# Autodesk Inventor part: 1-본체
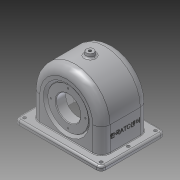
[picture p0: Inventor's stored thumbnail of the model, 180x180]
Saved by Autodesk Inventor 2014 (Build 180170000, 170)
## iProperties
Created: 2015-09
Part Number: 1-본체
Material: 알루미늄 6061
Document SubType Name: Modeling
Designer: Administrator
Density: 2.71 g/cm^3
Appearance: 알루미늄 - 평지
Mass: 723.361 g
Surface Area: 890.236 cm^2
Volume: 266.923 cm^3
Author: Administrator
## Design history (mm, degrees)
sketch "스케치2"
  geometry: L1 (57, 0)-(57, 47); L2 (-57, 47)-(-57, 0); L3 (-57, 0)-(57, 0); A1 r 57 centre (0, 47) between (57, 47) and (-57, 47); 1 further point
  constraints: 6 end point, 2 point on circle, 2 tangent, 1 centre point, 1 midpoint, 1 parallel, 1 perpendicular, 1 vertical, 1 vertical alignment
  dimensions: "d0" = 47 distance of A1.centre point (0, 0); "d1" = 57 radius of A1
extrude "돌출1" new body sketch "스케치2" distance "d2" = 38.5; taper "d3" = 0 deg
sketch "스케치4"
  geometry: L1 (70, -7)-(-70, -7); L2 (-70, -7)-(-70, 0); L3 (-70, 0)-(70, 0); L4 (70, 0)-(70, -7); L5 (57, 0)-(-57, 0) reference; 3 further points
  constraints: 8 end point, 2 midpoint, 2 parallel, 1 collinear, 1 horizontal, 1 perpendicular, 1 vertical alignment
  dimensions: "d6" = 7 distance of L1.end L2.end; "d7" = 140 distance of L2.end L3.end
extrude "돌출2" join sketch "스케치4" distance "d8" = 52; taper "d9" = 0 deg
sketch "스케치5"
  geometry: L1 (51, 0)-(51, -47); L2 (-51, -47)-(-51, 0); L3 (-51, 0)-(51, 0); L4 (-70, 0)-(70, 0) reference; L5 (57, -47)-(57, -7) reference; A1 r 51 centre (0, -47) between (-51, -47) and (51, -47); A2 r 57 centre (0, -47) between (-57, -47) and (57, -47) reference; 1 further point
  constraints: 6 end point, 2 point on circle, 2 tangent, 1 centre point, 1 collinear, 1 concentric, 1 parallel, 1 perpendicular, 1 vertical
  dimensions: "d10" = 6 distance between parallel lines of L5 L1
extrude "돌출3" cut sketch "스케치5" distance "d11" = 33.5; taper "d12" = 0 deg
sketch "스케치6"
  geometry: L1 (-33.5, 47)-(-33.5, 86.747); L2 (-33.5, 86.747)-(-19.5, 75); L3 (-19.5, 75)-(-19.5, 47); L4 (-19.5, 47)-(-33.5, 47); L5 (33.5, 0)-(-33.5, 0) reference; L6 (-33.5, 98)-(-33.5, 47) reference; L7 (-38.5, 104)-(-38.5, 47) reference; 1 further point
  constraints: 8 end point, 1 collinear, 1 parallel, 1 perpendicular, 1 vertical
  dimensions: "d13" = 47 distance between parallel lines of L4 L5; "d14" = 56 diameter of L2.end L4; "d15" = 50 deg angle of L2 L3; "d16" = 19 distance between parallel lines of L3 L7
revolve "회전1" sketch "스케치6" stored, may be unused: angle "d17" = 90 deg
sketch "스케치7"
  geometry: C1 r 31 at (0, 0); A1 r 57 centre (0, 0) between (-57, 0) and (57, 0) reference; 1 further point
  constraints: 1 centre point, 1 concentric
  dimensions: "d18" = 62 diameter of C1
extrude "돌출4" join sketch "스케치7" distance "d19" = 10; taper "d20" = 0 deg
node "작업 평면2"
  node "작업 평면1"
sketch "스케치9"
  geometry: C1 r 6 at (0, 0); 1 further point
  constraints: 1 centre point, 1 coincident
  dimensions: "d22" = 12 diameter of C1
extrude "돌출5" join sketch "스케치9" stored distance "d23" = 10; taper "d24" = 10 deg
sketch "스케치12"
  geometry: L1 (-38.5, 84.416)-(-38.5, 47); L2 (-38.5, 47)-(-35.5, 47); L3 (-35.5, 47)-(-35.5, 80); L4 (-35.5, 80)-(-33.237, 80); L5 (-33.237, 80)-(-38.5, 84.416); L6 (-38.5, 104)-(-38.5, 47) reference; L7 (-33.5, 86.747)-(-19.5, 75) reference; 1 further point
  constraints: 10 end point, 3 parallel, 1 collinear, 1 perpendicular, 1 vertical
  dimensions: "d34" = 47 distance from line of L2 point (0, 0); "d35" = 5 distance between parallel lines of L5 L7; "d36" = 66 diameter of L4 L2; "d37" = 3 distance between parallel lines of L1 L3
revolve "회전2" sketch "스케치12" stored, may be unused: angle "d38" = 90 deg
sketch "스케치13"
  geometry: L1 (0, 47)-(0, 0)
  constraints: 2 end point, 1 vertical
  dimensions: "d39" = 47 distance of L1.start L1.end
hole "구멍2" sketch "스케치13" at (0, 0) diameter "d40" = 40; stored, may be unused: countersink angle "d44" = 90 deg, drill point angle "d46" = 0 deg; dims "d41" = 6, "d42" = 4, "d43" = 2, "d45" = 3
hole "구멍3" diameter "d49" = 4.459; stored, may be unused: countersink angle "d53" = 90 deg, drill point angle "d55" = 0 deg; dims "d50" = 20, "d51" = 4, "d52" = 2, "d54" = 10, "d58" = 10, "d59" = 10
sketch "스케치14"
  geometry: L1 (0, -47)-(0, 0); L2 (0, 0)-(0, 28)
  constraints: 4 end point, 1 collinear, 1 vertical
  dimensions: "d56" = 47 distance of L1.start L1.end; "d57" = 28 distance of L1.end L2.end
hole "구멍4" sketch "스케치14" at (0, 28) diameter "d60" = 2.459; stored, may be unused: countersink angle "d64" = 90 deg, drill point angle "d66" = 118 deg; dims "d61" = 7, "d62" = 4, "d63" = 2, "d65" = 9
sketch "스케치15"
  geometry: L1 (0, 47)-(0, 0); L2 (0, 0)-(0, -24)
  constraints: 4 end point, 1 collinear, 1 vertical
  dimensions: "d70" = 47 distance of L1.start L1.end; "d71" = 24 distance of L1.end L2.end
hole "구멍5" sketch "스케치15" at (0, -24) diameter "d72" = 2.459; stored, may be unused: countersink angle "d76" = 90 deg, drill point angle "d78" = 118 deg; dims "d73" = 6, "d74" = 4, "d75" = 2, "d77" = 8
fillet "모깎기1" dims "d82" = 7
sketch "스케치16"
  geometry: L1 (63, 52)-(1, 52); L2 (1, 52)-(1, 8); L3 (1, 52)-(1, 96)
  constraints: 6 end point, 1 collinear, 1 horizontal, 1 perpendicular
  dimensions: "d83" = 62 distance of L1.start L1.end; "d84" = 44 distance of L1.end L2.end; "d85" = 44 distance of L1.end L3.end
hole "구멍6" sketch "스케치16" diameter "d86" = 5; stored, may be unused: countersink angle "d90" = 90 deg, drill point angle "d92" = 0 deg; dims "d87" = 5, "d88" = 4, "d89" = 2, "d91" = 8
hole "구멍7" sketch "스케치16" diameter "d93" = 5; stored, may be unused: countersink angle "d97" = 90 deg, drill point angle "d99" = 0 deg; dims "d94" = 5, "d95" = 4, "d96" = 2, "d98" = 8
hole "구멍8" sketch "스케치16" diameter "d100" = 5; stored, may be unused: countersink angle "d104" = 90 deg, drill point angle "d106" = 0 deg; dims "d101" = 5, "d102" = 4, "d103" = 2, "d105" = 8
fillet "모깎기2" dims "d107" = 14
fillet "모깎기3" dims "d108" = 9
chamfer "모따기1" distance "d109" = 1; stored, may be unused: second distance "d110" = 2, angle "d111" = 45 deg
fillet "모깎기4" dims "d112" = 3
fillet "모깎기5" dims "d113" = 1
fillet "모깎기6" dims "d114" = 0.5
fillet "모깎기7" dims "d115" = 3
fillet "모깎기8" dims "d116" = 3
sketch "스케치17"
  geometry: L1 (13.398, -17.573)-(13.398, 66.573); L2 (13.398, 66.573)-(20.602, 66.573); L3 (20.602, 66.573)-(20.602, -17.573); L4 (20.602, -17.573)-(13.398, -17.573); L5 (47, 69.5)-(47, -20.5) reference; L6 (0, -14)-(39, -14) reference; 4 further points
  constraints: 3 midpoint, 1 horizontal alignment, 2 other
  dimensions: "d117" = 30 distance from line of L5 point (17, -17.573); "d118" = 38.5 distance from line of L6 point (20.602, 24.5) (derived)
feature "엠보싱1" sketch "스케치17" dims "d10" = 6, "d119" = 0.5, "d120" = 0
node "솔리드1"
mirror "대칭1"
pattern_circular "원형 패턴1" dims angle "d68" = 360 deg
pattern_circular "원형 패턴2" dims angle "d80" = 360 deg
mirror "대칭2"
other parameters: "d21" = 6
